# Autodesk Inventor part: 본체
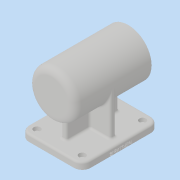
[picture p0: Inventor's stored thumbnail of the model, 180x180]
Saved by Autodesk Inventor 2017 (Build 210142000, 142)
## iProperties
Part Number: 본체
Material: 일반
Document SubType Name: Modeling
Designer: 222
Density: 1 g/cm^3
Appearance: 기본값
Mass: 380.103 g
Surface Area: 757.984 cm^2
Volume: 380.103 cm^3
Author: 222
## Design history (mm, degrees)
sketch "스케치1"
  geometry: C1 r 34 at (0, 0); 1 further point
  constraints: 1 centre point, 1 coincident
  dimensions: "d0" = 68 diameter of C1
extrude "돌출1" new body sketch "스케치1" stored distance "d1" = 112; taper "d2" = 0 deg
sketch "스케치3"
  geometry: L1 (0, 50)-(0, -56); L2 (0, -56)-(21, -56); L3 (21, -56)-(21, -41); L4 (21, -41)-(24, -41); L5 (24, -41)-(24, 13); L6 (24, 13)-(21, 13); L7 (21, 13)-(21, 25); L8 (21, 25)-(17.5, 25); L9 (17.5, 25)-(17.5, 43); L10 (17.5, 43)-(16, 43); L11 (16, 43)-(16, 47); L12 (16, 47)-(10.5, 47); L13 (10.5, 47)-(10.5, 50); L14 (10.5, 50)-(0, 50); L15 (-34, -56)-(34, -56) reference; 1 further point
  constraints: 28 end point, 12 perpendicular, 2 point on line, 1 midpoint, 1 vertical, 1 vertical alignment
  dimensions: "d15" = 21 diameter of L13 L1; "d16" = 32 diameter of L11 L1; "d17" = 35 diameter of L9 L1; "d18" = 3 distance of L12.end L13.end; "d19" = 4 distance of L10.end L11.end; "d20" = 18 distance of L8.end L9.end; "d21" = 12 distance of L6.end L7.end; "d22" = 54 distance of L4.end L5.end; "d23" = 15 distance of L2.end L3.end; "d24" = 42 diameter of L3 L1; "d25" = 48 diameter of L5 L1
revolve "회전1" sketch "스케치3" stored, may be unused: angle "d26" = 90 deg
fillet "모깎기1" dims "d27" = 10
sketch "스케치4"
  geometry: 2 further points
  constraints: 1 vertical alignment
  dimensions: "d28" = 26 distance of point (0, 0) point (0, 26)
hole "구멍1" sketch "스케치4" at (0, 26) diameter "d29" = 3.242; stored, may be unused: countersink angle "d33" = 90 deg, drill point angle "d35" = 118 deg; dims "d30" = 8, "d31" = 4, "d32" = 2, "d34" = 11
sketch "스케치5"
  geometry: L1 (-64, 56)-(-74, 56); L2 (-74, 56)-(-74, -56); L3 (-74, -56)-(-64, -56); L4 (-64, -56)-(-64, 56); 2 further points
  constraints: 8 end point, 3 perpendicular, 1 horizontal, 1 horizontal alignment, 1 midpoint
  dimensions: "d39" = 112 distance of L1.end L2.end; "d40" = 10 distance of L2.end L3.end; "d41" = 74 distance from line of L2 point (0, 0)
extrude "돌출2" join sketch "스케치5" stored distance "d42" = 90; taper "d43" = 0 deg
fillet "모깎기2" dims "d44" = 12
sketch "스케치6"
  geometry: L1 (0, 0)-(66, 0) reference; L2 (-12, 100)-(-12, 12) reference; 2 further points
  dimensions: "d45" = 12 distance from line of L1 point (0, 12); "d46" = 12 distance from line of L2 point (0, 12)
hole "구멍2" sketch "스케치6" at (0, 12) diameter "d47" = 5.5; stored, may be unused: countersink angle "d51" = 90 deg, drill point angle "d53" = 0 deg; dims "d48" = 6, "d49" = 9.5, "d50" = 5.4, "d52" = 8
sketch "스케치7"
  geometry: L1 (-1, 60)-(-1, 52); L2 (-1, 52)-(29, 52); L3 (29, 52)-(29, 18); L4 (29, 18)-(37, 18); L5 (37, 18)-(37, 52); L6 (37, 52)-(67, 52); L7 (67, 52)-(67, 60); L8 (67, 60)-(37, 60); L9 (37, 60)-(37, 94); L10 (37, 94)-(29, 94); L11 (29, 94)-(29, 60); L12 (-1, 60)-(29, 60); L13 (37, 52)-(29, 60); 2 further points
  constraints: 26 end point, 8 perpendicular, 7 point on line, 2 collinear, 1 coincident, 1 midpoint, 1 vertical
  dimensions: "d60" = 8 distance of L1.start L1.end; "d61" = 8 distance of L9.end L10.end; "d62" = 76 distance between parallel lines of L10 L4; "d63" = 68 distance between parallel lines of L7 L1
extrude "돌출3" join sketch "스케치7" stored distance "d64" = 90; taper "d65" = 0 deg
fillet "모깎기3" dims "d66" = 3
fillet "모깎기4" dims "d67" = 3
fillet "모깎기5" dims "d68" = 3
chamfer "모따기1" distance "d69" = 1; stored, may be unused: second distance "d70" = 2, angle "d71" = 45 deg
fillet "모깎기7" dims "d73" = 0.3
sketch "스케치8"
  geometry: L1 (-44, -74)-(44, -74) reference; L2 (56, -74)-(56, -67) reference; 2 further points
  constraints: 1 other
  dimensions: "d74" = 3 distance from line of L1 point (0, -71); "d75" = 56 distance from line of point (0, -71) L2
feature "엠보싱1" sketch "스케치8" dims "d76" = 0.5, "d77" = 0
fillet "모깎기8" dims "d78" = 3
node "솔리드1"
pattern_circular "원형 패턴1" dims angle "d37" = 360 deg
pattern_linear "직사각형 패턴1" dims "d56" = 66, "d59" = 88
